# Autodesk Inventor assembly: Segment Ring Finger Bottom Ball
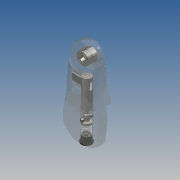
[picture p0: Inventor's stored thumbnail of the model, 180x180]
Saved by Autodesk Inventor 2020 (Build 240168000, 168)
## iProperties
Created: 2019-10
Part Number: Segment Ring Finger Bottom Ball
Document SubType Name: Assembly
Designer: yello
Author: yello
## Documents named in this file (8)
- C:\Users\yello\Documents\Mechanical Hand\Prototype 2 (Realistic Hand)\Segment Ring Finger Bottom Ball.iam
- C:\Users\yello\Documents\Mechanical Hand\Prototype 2 (Realistic Hand)\Segment Ring Finger Bottom.ipt
- C:\Users\yello\Documents\Mechanical Hand\Prototype 2 (Realistic Hand)\Lock.ipt
- C:\Users\yello\Documents\Mechanical Hand\Prototype 2 (Realistic Hand)\Push Part.ipt
- C:\Users\yello\Documents\Mechanical Hand\Prototype 2 (Realistic Hand)\Ball.ipt
- C:\Users\yello\Documents\Mechanical Hand\Prototype 2 (Realistic Hand)\Spring.ipt
- C:\Users\yello\Documents\Mechanical Hand\Prototype 2 (Realistic Hand)\Plug 2.ipt
- C:\Users\yello\Documents\Mechanical Hand\Prototype 2 (Realistic Hand)\Bearings.iam
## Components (8 placed, 7 different names)
1. Segment Ring Finger Bottom:1 — Mate:1, Mate:4, Mate:5, Mate:6, Mate:7, Mate:8, Mate:9, Mate:10, Flush:1
2. Lock:1 — Mate:2, Mate:3, Mate:4
3. Push Part:1 — Mate:1, Mate:2, Mate:3
4. Ball:1 — Mate:5
5. Ball:2 — Mate:6
6. Spring:1 — Mate:7
7. Plug 2:1 — Mate:8, Mate:9
8. Bearings:1 [sub-assembly] — Mate:10, Flush:1
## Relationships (11: Mate 10, Flush 1)
- Mate:1: Segment Ring Finger Bottom:1 ↔ Push Part:1
- Mate:2: Lock:1 ↔ Push Part:1
- Mate:3: Lock:1 ↔ Push Part:1
- Mate:4: Segment Ring Finger Bottom:1 ↔ Lock:1
- Mate:5: Segment Ring Finger Bottom:1 ↔ Ball:1
- Mate:6: Segment Ring Finger Bottom:1 ↔ Ball:2
- Mate:7: Segment Ring Finger Bottom:1 ↔ Spring:1
- Mate:8: Segment Ring Finger Bottom:1 ↔ Plug 2:1
- Mate:9: Segment Ring Finger Bottom:1 ↔ Plug 2:1
- Mate:10: Segment Ring Finger Bottom:1 ↔ Bearings:1
- Flush:1: Segment Ring Finger Bottom:1 ↔ Bearings:1
